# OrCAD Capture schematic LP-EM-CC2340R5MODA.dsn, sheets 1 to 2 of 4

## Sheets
1 1_RF: size A3; title: LP-EM-CC2340R5MODA
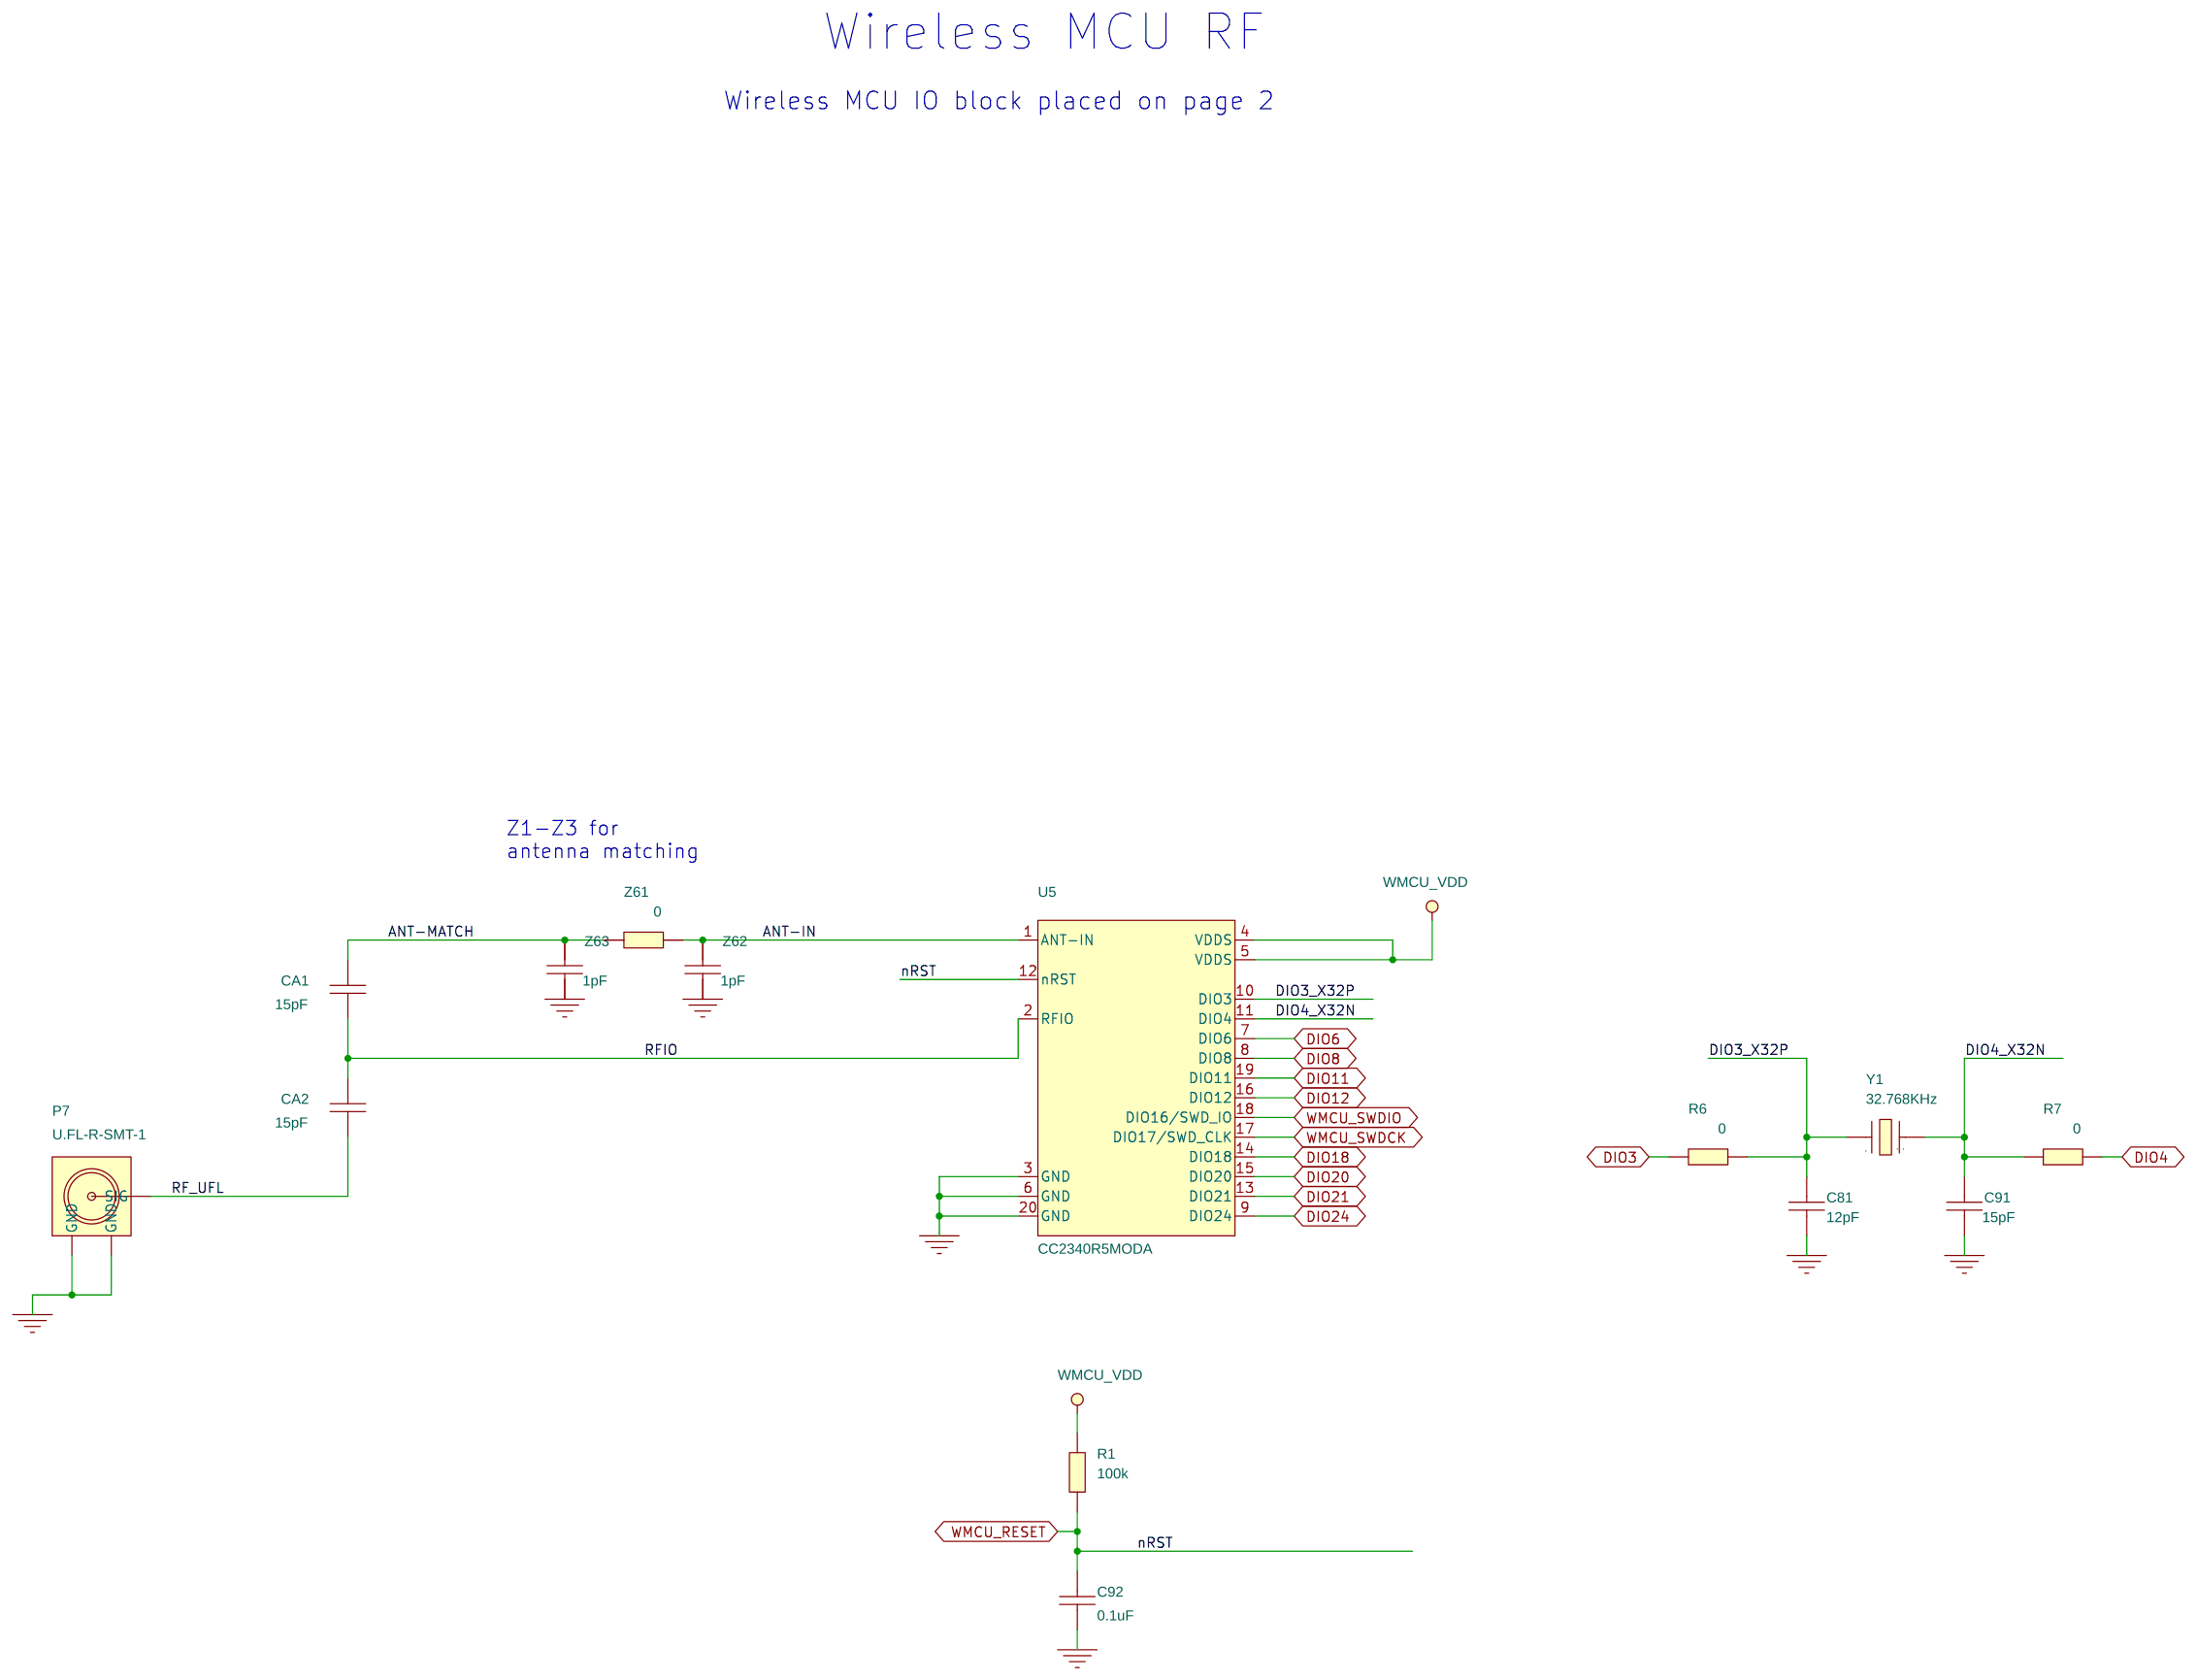
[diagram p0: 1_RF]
2 2_Peripherals: size A3
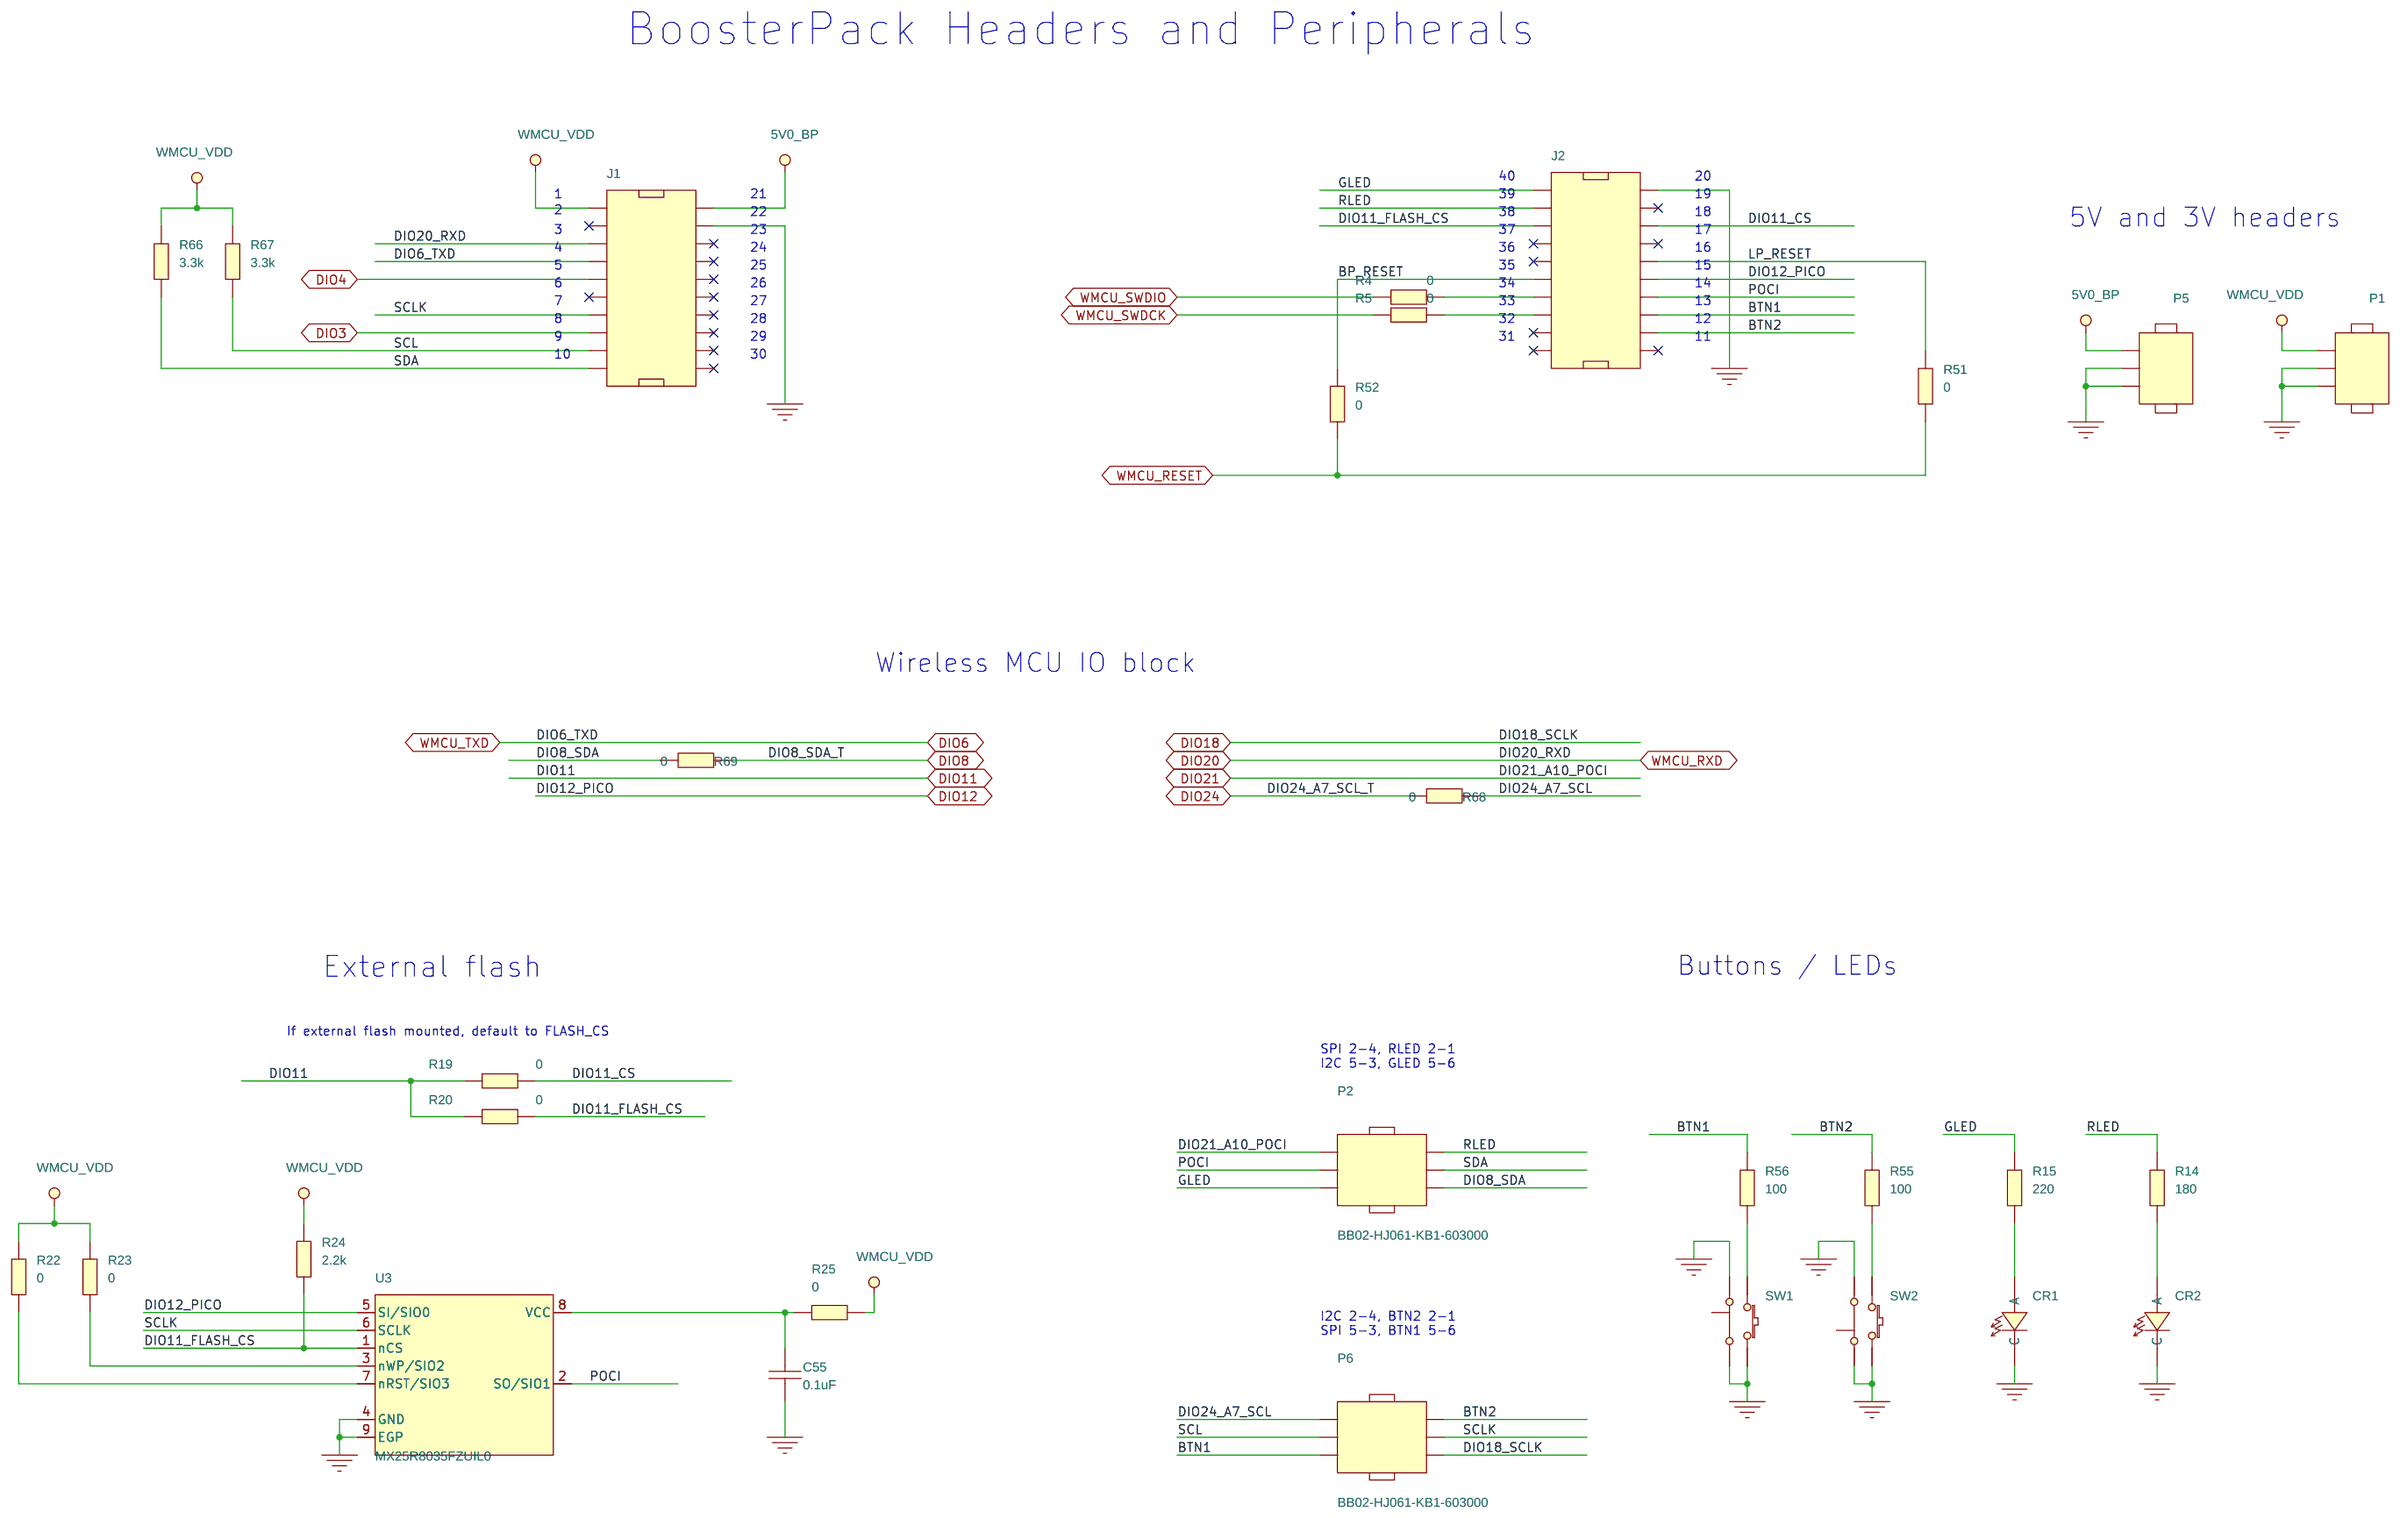
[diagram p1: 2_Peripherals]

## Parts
sheet 1_RF
C81  12pF  [CAPC0603X35B2N]
C91  15pF  [CAPC0603X35B2N]
C92  0.1uF  [CAPC0603X35B2N]
CA1  15pF  [CAPC0603X35B2N]
CA2  15pF  [CAPC0603X35B2N]
P7  U.FL-R-SMT-1  [HIROSE_UFLRSMT_A2N]
R1  100k  [RESC0603X35B2N]
R6  0  [RESC0603X35B2N]
R7  0  [RESC0603X35B2N]
U5  CC2340R5MODA  [MODULE_CC2340R5MODA_A2N]
Y1  32.768KHz  [XTAL_TZ3359DAAO73_A2N]
Z61  0  [RESC0603X35B2N]
Z62  1pF  [CAPC0603X35B2N]
Z63  1pF  [CAPC0603X35B2N]
sheet 2_Peripherals
C55  0.1uF  [CAPC0603X35B2N]
CR1  LPL296-J2L2-25  [LEDC1707X65N]
CR2  LS L296-P2Q2-1  [LEDC1708X67N]
J1  SSQ-110-23-L-D  [SAMTEC_SSQ11023LD_A2B]
J2  SSQ-110-23-L-D  [SAMTEC_SSQ11023LD_A2B]
P1  BB02-HC031-KB1-603000  [GRADCONN_BB02HC031KB1603000_A2B]
P2  BB02-HJ061-KB1-603000  [GRADCONN_BB02HJ061KB1603000_A2B]
P5  BB02-HC031-KB1-603000  [GRADCONN_BB02HC031KB1603000_A2B]
P6  BB02-HJ061-KB1-603000  [GRADCONN_BB02HJ061KB1603000_A2B]
R4  0  [RESC1608X55A2N]
R5  0  [RESC1608X55A2N]
R14  180  [RESC1005X40B2N]
R15  220  [RESC1005X40B2N]
R19  0  [RESC1608X55A2N]
R20  0  [RESC1608X55A2N]
R22  0  [RESC1608X55A2N]
R23  0  [RESC1608X55A2N]
R24  2.2k  [RESC1005X40B2N]
R25  0  [RESC1608X55A2N]
R51  0  [RESC1608X55A2N]
R52  0  [RESC1608X55A2N]
R55  100  [RESC1005X40B2N]
R56  100  [RESC1005X40B2N]
R66  3.3k  [RESC1005X40B2N]
R67  3.3k  [RESC1005X40B2N]
R68  0  [RESC1005X40A2N]
R69  0  [RESC1005X40A2N]
SW1  1188E-1K2  [SW_1188E1K2V_A2N]
SW2  1188E-1K2  [SW_1188E1K2V_A2N]
U3  MX25R8035FZUIL0  [SON50P300X200X60-9B2N]

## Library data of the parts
C81 = CAPACITOR: CAPACITOR, CERAMIC C0G/NP0, 12pF, 50V, -2%/+2%, -55DEGC/+125DEGC, 0201, SMD; ALT_SYMBOLS: CAPC0603X35B2L,CAPC0603X35B2M; Additional Datasheet URL: https://www.murata.com/en-us/products/productdetail?partno=GRM0335C1H120GA01%23; AutoDoc File: https://notefied-dynamic-precision.com/DB/Apps/Desktop/Item/Object.aspx?id=113345; BU Name: TEXAS INSTRUMENTS NORWAY; Budget Currency: EUR; Budget Price: 0.007; Budgetary Price: .00506 USD; Country of Origin: China, Japan, Philippines; Datasheet URL: https://search.murata.co.jp/Ceramy/image/img/A01X/G101/ENG/GRM0335C1H120GA01-01A.pdf; Datasheet URL 1: http://psearch.murata.com/capacitor/product/GRM1555C1H120JA01%23.pdf; Datasheet URL 2: http://search.murata.co.jp/Ceramy/image/img/w_hinm/L0005E.pdf; Definied Quality: INDUSTRIAL; Dielectric Type: C0G/NP0; Esd Level: N/A; Lead Time: 23; LifeCycle Status: ACTIVE; MPN: CAPACITOR_0402_12pF_C0G/NP0_M_+/-5%_50V; MPN Status: ACTIVE; MSL: N/A; MTBF: N/A; MTBF Standard: N/A; Manufacturer: MANUFACTURER SELECTION; Mass: 0.00033g; Max Oper Temp: +125DEGC; Max Tol: +5%; Maximum Operating Temperature: +125DEGC; Maximum Tolerance: +2%; Min Oper Temp: -55DEGC; Min Tol: -5%; Minimum Operating Temperature: -55DEGC; Minimum Tolerance: -2%; Mounting Type: SMD; NOTE Status: PREFERRED; NOTEfied URL: https://dev-webinterface.dpserver.no/item/31254676; Old Footprint: CAPC1005X60N; PCB Package: 0201; Packing Size: 15000; Packing Type: Tape & Reel; Part Number: 02-10307; Part Type: Capacitor|CERAMIC|0201|STANDARD; REACH/SVHC Compliance: Compliant; REACH/SVHC Details: SVHC List Version Jan 19, 2021; REACH/SVHC Source: REACH Declaration; REACH/SVHC Status: Unaffected; REACH/SVHC_COMPLIANCE: COMPLIANT; REACH/SVHC_DETAILS: SVHC LIST VERSION Dec 17, 2015; REACH/SVHC_SOURCE: REACH DECLARATION; REACH/SVHC_STATUS: UNAFFECTED; ROHS: Compliant; Rated Voltage: 50V; Revision: R003; RoHS Status: ROHS_COMPLIANT; Rtd Voltage: 50V; Status: Released; Texas Part Status: Under Review; Type: Capacitor; Vendor: MURATA; Vendor Part Number: GRM0335C1H120GA01D; Vendor Part Status: Active; WEIGHT: 0.0016g
C91 = CAPACITOR: CAPACITOR, CERAMIC C0G/NP0, 15pF, 50V, -2%/+2%, -55DEGC/+125DEGC, 0201, SMD; ALT_SYMBOLS: CAPC0603X35B2L,CAPC0603X35B2M; Additional Datasheet URL: https://www.murata.com/en-us/products/productdetail?partno=GRM0335C1H150GA01%23; AutoDoc File: https://notefied-dynamic-precision.com/DB/Apps/Desktop/Item/Object.aspx?id=114571; BU Name: TEXAS INSTRUMENTS NORWAY; Budget Currency: EUR; Budget Price: 0.006; Budgetary Price: .0032 USD; Client Status: UNDER_REVIEW; Country of Origin: China, Japan, Philippines; Datasheet URL: https://search.murata.co.jp/Ceramy/image/img/A01X/G101/ENG/GRM0335C1H150GA01-01A.pdf; Datasheet URL 1: http://psearch.murata.com/capacitor/product/GRM1555C1H150JA01%23.pdf; Datasheet URL 2: http://psearch.en.murata.com/capacitor/product/GRM1555C1H150JA01%23.html; Definied Quality: INDUSTRIAL; Dielectric Type: C0G/NP0; Esd Level: N/A; Lead Time: 11; LifeCycle Status: ACTIVE; MPN: CAPACITOR_0402_12pF_C0G/NP0_M_+/-5%_50V; MPN Status: ACTIVE; MSL: N/A; MTBF: N/A; MTBF Standard: N/A; Manufacturer: MANUFACTURER SELECTION; Mass: 0.00033g; Max Oper Temp: +125DEGC; Max Tol: +5%; Maximum Operating Temperature: +125DEGC; Maximum Tolerance: +2%; Min Oper Temp: -55DEGC; Min Tol: -5%; Minimum Operating Temperature: -55DEGC; Minimum Tolerance: -2%; Mounting Type: SMD; NOTE Status: PREFERRED; NOTEfied URL: https://dev-webinterface.dpserver.no/item/20744949; Old Footprint: CAPC1005X60N; PCB Package: 0201; Packing Size: 15000; Packing Type: Tape & Reel; Part Number: 02-09323; Part Type: Capacitor|CERAMIC|0201|STANDARD; REACH/SVHC Compliance: Compliant; REACH/SVHC Details: SVHC List Version Jan 15, 2019; REACH/SVHC Source: REACH Declaration; REACH/SVHC Status: Unaffected; REACH/SVHC_COMPLIANCE: COMPLIANT; REACH/SVHC_DETAILS: SVHC List Version Jan 12, 2017; REACH/SVHC_SOURCE: REACH DECLARATION; REACH/SVHC_STATUS: UNAFFECTED; ROHS: Compliant; Rated Voltage: 50V; Revision: R010; RoHS Status: ROHS_COMPLIANT; Rtd Voltage: 50V; Status: Released; Texas Part Status: Under Review; Type: Capacitor; Vendor: MURATA; Vendor Part Number: GRM0335C1H150GA01D; Vendor Part Status: Active; WEIGHT: 0.0016g
C92 = CAPACITOR: CAPACITOR, CERAMIC X7S, 0.1uF, 10V, -10%/+10%, -55DEGC/+125DEGC, 0201, SMD; ALT_SYMBOLS: CAPC0603X35B2L,CAPC0603X35B2M; Additional Datasheet URL: https://www.murata.com/en-us/products/productdetail?partno=GRM033C71A104KE14%23; AutoDoc File: https://notefied-dynamic-precision.com/DB/Apps/Desktop/Item/Object.aspx?id=115293; BU Name: TEXAS INSTRUMENTS NORWAY; Budgetary Price: .01328 USD; Client Status: UNDER_REVIEW; Country of Origin: China, Japan, Philippines, Singapore; Datasheet URL: https://search.murata.co.jp/Ceramy/image/img/A01X/G101/ENG/GRM033C71A104KE14-01A.pdf; Datasheet URL 1: http://psearch.en.murata.com/capacitor/product/GRM155R71E104KE14%23.pdf; Datasheet URL 2: http://search.murata.co.jp/Ceramy/image/img/w_hinm/L0005E.pdf; Dielectric Type: X7S; Lead Time: 23; LifeCycle Status: ACTIVE; MPN: GRM155R70J104KA01D; MPN Status: ACTIVE; Manufacturer: MURATA; Mass: 0.00033g; Max Oper Temp: +125DEGC; Max Tol: +10%; Maximum Operating Temperature: +125DEGC; Maximum Tolerance: +10%; Min Oper Temp: -55DEGC; Min Tol: -10%; Minimum Operating Temperature: -55DEGC; Minimum Tolerance: -10%; Mounting Type: SMD; NOTE Status: PREFERRED; NOTEfied URL: https://dev-webinterface.dpserver.no/item/31254761; Old Footprint: CAPC1005X60N,0402; PCB Package: 0201; Packing Size: 15000; Packing Type: Tape & Reel; Part Number: 02-10308; Part Type: Capacitor|CERAMIC|0201|STANDARD; REACH/SVHC Compliance: Compliant; REACH/SVHC Details: SVHC List Version Jan 19, 2021; REACH/SVHC Source: REACH Declaration; REACH/SVHC Status: Unaffected; REACH/SVHC_COMPLIANCE: COMPLIANT; REACH/SVHC_DETAILS: SVHC LIST VERSION Jun 20, 2016; REACH/SVHC_SOURCE: REACH DECLARATION; REACH/SVHC_STATUS: UNAFFECTED; ROHS: Compliant; Rated Voltage: 10V; Revision: R003; RoHS Status: ROHS_COMPLIANT; Rtd Voltage: 25V; Status: Released; Texas Part Status: Under Review; Type: Capacitor; Vendor: MURATA; Vendor Part Number: GRM033C71A104KE14D; Vendor Part Status: Active; WEIGHT: 0.0016g
CA1 CA2 = CAPACITOR: CAPACITOR, CERAMIC C0G/NP0, 15pF, 50V, -2%/+2%, -55DEGC/+125DEGC, 0201, SMD; ALT_SYMBOLS: CAPC0603X35B2L,CAPC0603X35B2M; Additional Datasheet URL: https://www.murata.com/en-us/products/productdetail?partno=GRM0335C1H150GA01%23; AutoDoc File: https://notefied-dynamic-precision.com/DB/Apps/Desktop/Item/Object.aspx?id=113345; BU Name: TEXAS INSTRUMENTS NORWAY; Budget Currency: EUR; Budget Price: 0.007; Budgetary Price: .0032 USD; Country of Origin: China, Japan, Philippines; Datasheet URL: https://search.murata.co.jp/Ceramy/image/img/A01X/G101/ENG/GRM0335C1H150GA01-01A.pdf; Datasheet URL 1: http://psearch.murata.com/capacitor/product/GRM1555C1H120JA01%23.pdf; Datasheet URL 2: http://search.murata.co.jp/Ceramy/image/img/w_hinm/L0005E.pdf; Definied Quality: INDUSTRIAL; Dielectric Type: C0G/NP0; Esd Level: N/A; Lead Time: 11; LifeCycle Status: ACTIVE; MPN: CAPACITOR_0402_12pF_C0G/NP0_M_+/-5%_50V; MPN Status: ACTIVE; MSL: N/A; MTBF: N/A; MTBF Standard: N/A; Manufacturer: MANUFACTURER SELECTION; Mass: 0.00033g; Max Oper Temp: +125DEGC; Max Tol: +5%; Maximum Operating Temperature: +125DEGC; Maximum Tolerance: +2%; Min Oper Temp: -55DEGC; Min Tol: -5%; Minimum Operating Temperature: -55DEGC; Minimum Tolerance: -2%; Mounting Type: SMD; NOTE Status: PREFERRED; NOTEfied URL: https://dev-webinterface.dpserver.no/item/20744949; Old Footprint: CAPC1005X60N; PCB Package: 0201; Packing Size: 15000; Packing Type: Tape & Reel; Part Number: 02-09323; Part Type: Capacitor|CERAMIC|0201|STANDARD; REACH/SVHC Compliance: Compliant; REACH/SVHC Details: SVHC List Version Jan 15, 2019; REACH/SVHC Source: REACH Declaration; REACH/SVHC Status: Unaffected; REACH/SVHC_COMPLIANCE: COMPLIANT; REACH/SVHC_DETAILS: SVHC LIST VERSION Dec 17, 2015; REACH/SVHC_SOURCE: REACH DECLARATION; REACH/SVHC_STATUS: UNAFFECTED; ROHS: Compliant; Rated Voltage: 50V; Revision: R010; RoHS Status: ROHS_COMPLIANT; Rtd Voltage: 50V; Status: Released; Texas Part Status: Under Review; Type: Capacitor; Vendor: MURATA; Vendor Part Number: GRM0335C1H150GA01D; Vendor Part Status: Active; WEIGHT: 0.0016g
P7 = CONN_COAX_1_P_2_UFL: CONNECTOR, COAX, RF, MALE, STRAIGHT, 1 PIN(S), SMD; ALT_SYMBOLS: HIROSE_UFLRSMT_A2L,HIROSE_UFLRSMT_A2M; Additional Datasheet URL: https://www.hirose.com/en/product/p/CL0331-0472-2-01; Budgetary Price: .7575 USD; CLASS: IO; Country of Origin: Japan; Datasheet URL: https://www.hirose.com/en/product/document?clcode=CL0331-0472-2-01&productname=U.FL-R-SMT-1(01)&series=U.FL&documenttype=Catalog&lang=en&documentid=en_U.FL_CAT; Lead Time: 12; Mass: 0.0157g; Maximum Operating Temperature: +105DEGC; Minimum Operating Temperature: -40DEGC; Mounting Type: SMD; NOTEfied URL: https://dev-webinterface.dpserver.no/item/7312664; Number of Positions: 1; Packing Size: 100; Packing Type: Bag; Part Number: 06-01471; Part Type: Connector|COAX|RF; ROHS: Compliant; Rated Current: N/A; Rated Voltage: 200V; Status: Released; Type: Connector; Vendor: HIROSE; Vendor Part Number: U.FL-R-SMT-1(01); Vendor Part Status: Active
R1 = RESISTOR: RESISTOR, THICK FILM, 100k, -5%/+5%, 0.05W, 30V, -55DEGC/+155DEGC, 0201, SMD; ALT_SYMBOLS: RESC0603X35B2L,RESC0603X35B2M; Additional Datasheet URL: https://www.vishay.com/en/product/20052/; Budgetary Price: .005 EUR; Country of Origin: China, Israel, Taiwan; Datasheet URL: https://www.vishay.com/docs/20052/crcw0201e3.pdf; Lead Time: 20; Mass: 0.00017g; Maximum Operating Temperature: +155DEGC; Maximum Temperature Coefficient: +200PPM/DEGC; Maximum Tolerance: +5%; Minimum Operating Temperature: -55DEGC; Minimum Temperature Coefficient: -200PPM/DEGC; Minimum Temperature Coeficient: -200PPM/DEGC; Minimum Tolerance: -5%; Mounting Type: SMD; NOTEfied URL: https://dev-webinterface.dpserver.no/item/7195810; PCB Package: 0201; Packing Size: 10000; Packing Type: Tape & Reel; Part Number: 01-04220; Part Type: Resistor|0201|STANDARD; REACH/SVHC Compliance: Compliant; REACH/SVHC Details: SVHC List Version Dec 17, 2015; REACH/SVHC Source: Material Declaration; REACH/SVHC Status: Unaffected; ROHS: Exempt; Rated Current: N/A; Rated Power: 0.05W; Rated Voltage: 30V; Resistor Type: THICK FILM; Revision: R008; Status: Released; Texas Part Number: TEXAS_00013; Texas Part Status: Under Review; Type: Resistor; Vendor: VISHAY; Vendor Part Number: CRCW0201100KJNED; Vendor Part Status: Active
R6 R7 Z61 = RESISTOR: RESISTOR, THICK FILM, JUMPER, 0, 0R/+0.05R, 0.5A, -55DEGC/+125DEGC, 0201, SMD; ALT_SYMBOLS: RESC0603X35B2L,RESC0603X35B2M; Additional Datasheet URL: https://www.koaspeer.com/products/resistors/general-purpose/rk73z/; Budgetary Price: .012 EUR; Country of Origin: Missing Info; Datasheet URL: https://www.koaspeer.com/pdfs/RK73Z.pdf; Lead Time: 14; Mass: 0.00014g; Maximum Operating Temperature: +125DEGC; Maximum Temperature Coefficient: N/A; Maximum Tolerance: +0.05R; Minimum Operating Temperature: -55DEGC; Minimum Temperature Coefficient: N/A; Minimum Temperature Coeficient: N/A; Minimum Tolerance: 0R; Mounting Type: SMD; NOTEfied URL: https://dev-webinterface.dpserver.no/item/7239994; PCB Package: 0201; Packing Size: 10000; Packing Type: Tape & Reel; Part Number: 01-18293; Part Type: Resistor|0201|JUMPER; ROHS: Exempt; Rated Current: 0.5A; Rated Power: N/A; Rated Voltage: N/A; Resistor Type: THICK FILM; Revision: R013; Status: Released; Type: Resistor; Vendor: KOA SPEER; Vendor Part Number: RK73Z1HTTC; Vendor Part Status: NRND
U5 = IC_RF_CC2340R5MODA: IC, MODULE, CC2340R5MODA; Additional Datasheet URL: https://www.ti.com/; Country of Origin: Missing Info; Datasheet URL: N/A; Mass: N/A; Maximum Operating Temperature: N/A; Minimum Operating Temperature: N/A; Mounting Type: SMD; NOTEfied URL: https://dev-webinterface.dpserver.no/item/59600491; Notes: Custom item; Packing Size: N/A; Packing Type: Missing Info; Part Number: 18-39305; Part Type: IC|MODULE|WIRELESS; ROHS: Missing Info; Status: Released; Texas Part Status: Under Review; Type: IC; Vendor: TEXAS INSTRUMENTS; Vendor Part Status: Preliminary
Y1 = XTAL: CRYSTAL, RESONATOR, 32.768KHz, -380PPM/+380PPM, -40DEGC/+125DEGC, SMD; ALT_SYMBOLS: XTAL_TZ3359DAAO73_A2L,XTAL_TZ3359DAAO73_A2M; Additional Datasheet URL: https://www.taisaw.com/products/searchA?param=TZ3359DAAO73; Capacitance: 7pF; Country of Origin: Missing Info; Datasheet URL: https://www.taisaw.com/assets/PDF/TZ3359DAAO73%20_Rev.1.pdf; Maximum Operating Temperature: +125DEGC; Maximum Stability: +380PPM; Maximum Tolerance: +20PPM; Minimum Operating Temperature: -40DEGC; Minimum Stability: -380PPM; Minimum Tolerance: -20PPM; Mounting Type: SMD; NOTEfied URL: https://dev-webinterface.dpserver.no/item/34987642; Notes: Non-standard part/non-catalogue part. Created on the basis of documentation provided by the customer (Texas Instruments).; Packing Size: 5000; Packing Type: Tape & Reel; Part Number: 12-01593; Part Type: Crystal|RESONATOR; REACH/SVHC Compliance: Missing Info; REACH/SVHC Details: N/A; REACH/SVHC Source: N/A; REACH/SVHC Status: Missing Info; ROHS: Compliant; Revision: R001; Status: Released; Texas Part Status: Under Review; Type: Crystal; Vendor: TAI-SAW; Vendor Part Number: TZ3359DAAO73; Vendor Part Status: Active
Z62 Z63 = CAPACITOR: CAPACITOR, CERAMIC C0G/NP0, 1pF, -0.1pF/+0.1pF, 50V, -55DEGC/+125DEGC, 0201, SMD; ALT_SYMBOLS: CAPC0603X35B2L,CAPC0603X35B2M; Additional Datasheet URL: https://pim.murata.com/en-us/pim/details/?productCategoryId=ceramicCapacitorSMD&partNum=GRM0335C1H1R0BA01%23; Budgetary Price: .01 EUR; Country of Origin: China, Japan, Philippines, Singapore, Thailand; Datasheet URL: https://pim.murata.com/asset/pim4/ceramicCapacitorSMD/GRM0335C1H1R0BA01-01A-EN_PDF_CERAMICCAPACITORSMD?lastModifiedDatetime=20250813140542; Dielectric Type: C0G/NP0; Lead Time: 24; Mass: 0.00033g; Maximum Operating Temperature: +125DEGC; Maximum Tolerance: +0.1pF; Minimum Operating Temperature: -55DEGC; Minimum Tolerance: -0.1pF; Mounting Type: SMD; NOTEfied URL: https://webinterface.notefied-dynamic-precision.com/item/7272567; PCB Package: 0201; Packing Size: 50000; Packing Type: Tape & Reel; Part Number: 02-06124; Part Type: Capacitor|CERAMIC|0201|STANDARD; REACH/SVHC Compliance: Compliant; REACH/SVHC Details: SVHC List Version Jan 23, 2024 (240); REACH/SVHC Source: REACH Declaration; REACH/SVHC Status: Unaffected; ROHS: Compliant; Rated Voltage: 50V; Status: Released; Texas Part Status: Under Review; Type: Capacitor; Vendor: MURATA; Vendor Part Number: GRM0335C1H1R0BA01J; Vendor Part Status: Active
C55 = CAPACITOR: CAPACITOR, CERAMIC X7S, 0.1uF, 10V, -10%/+10%, -55DEGC/+125DEGC, 0201, SMD; ALT_SYMBOLS: CAPC0603X35B2L,CAPC0603X35B2M; Additional Datasheet URL: https://www.murata.com/en-us/products/productdetail?partno=GRM033C71A104KE14%23; AutoDoc File: https://notefied-dynamic-precision.com/DB/Apps/Desktop/Item/Object.aspx?id=115293; BU Name: TEXAS INSTRUMENTS NORWAY; Budgetary Price: .01328 USD; Client Status: UNDER_REVIEW; Country of Origin: China, Japan, Philippines, Singapore; Datasheet URL: https://search.murata.co.jp/Ceramy/image/img/A01X/G101/ENG/GRM033C71A104KE14-01A.pdf; Datasheet URL 1: http://psearch.en.murata.com/capacitor/product/GRM155R71E104KE14%23.pdf; Datasheet URL 2: http://search.murata.co.jp/Ceramy/image/img/w_hinm/L0005E.pdf; Definied Quality: INDUSTRIAL; Dielectric Type: X7S; Esd Level: N/A; Lead Time: 23; LifeCycle Status: ACTIVE; MPN: CAPACITOR_0402_100nF_X7R_M_+/-10%_10V; MPN Status: ACTIVE; MSL: N/A; MTBF: N/A; MTBF Standard: N/A; Manufacturer: MANUFACTURER SELECTION; Mass: 0.00033g; Max Oper Temp: +125DEGC; Max Tol: +10%; Maximum Operating Temperature: +125DEGC; Maximum Tolerance: +10%; Min Oper Temp: -55DEGC; Min Tol: -10%; Minimum Operating Temperature: -55DEGC; Minimum Tolerance: -10%; Mounting Type: SMD; NOTE Status: PREFERRED; NOTEfied URL: https://dev-webinterface.dpserver.no/item/31254761; Old Footprint: CAPC1005X60N; PCB Package: 0201; Packing Size: 15000; Packing Type: Tape & Reel; Part Number: 02-10308; Part Type: Capacitor|CERAMIC|0201|STANDARD; REACH/SVHC Compliance: Compliant; REACH/SVHC Details: SVHC List Version Jan 19, 2021; REACH/SVHC Source: REACH Declaration; REACH/SVHC Status: Unaffected; REACH/SVHC_COMPLIANCE: COMPLIANT; REACH/SVHC_DETAILS: SVHC LIST VERSION Jun 20, 2016; REACH/SVHC_SOURCE: REACH DECLARATION; REACH/SVHC_STATUS: UNAFFECTED; ROHS: Compliant; Rated Voltage: 10V; Revision: R003; RoHS Status: ROHS_COMPLIANT; Rtd Voltage: 25V; Status: Released; Texas Part Status: Under Review; Type: Capacitor; Vendor: MURATA; Vendor Part Number: GRM033C71A104KE14D; Vendor Part Status: Active; WEIGHT: 0.0016g
CR1 = LED: OPTO, LED, InGaAlP, GREEN, 560nm, 1.8V TO 2.4V, 0.02A, 0603, SMD; ALT_SYMBOLS: LEDC1707X65L,LEDC1707X65M; Additional Datasheet URL: https://ams-osram.com/products/leds/color-leds/osram-smartled-0603-lp-l296; AutoDoc File: http://notefied-dynamic-precision.com/DB/Apps/Desktop/Item/Object.aspx?id=81622; Budget Currency: USD; Budget Price: 0.1263; CLASS: IC; Country of Origin: Missing Info; Datasheet URL: https://look.ams-osram.com/m/37da308c02be71bd/original/LP-L296.pdf; Datasheet URL 1: N/A; Datasheet URL 2: http://catalog.osram-os.com/jsp/download.jsp?rootPath=/media/&name=LP_L296.pdf&docPath=Graphics/00077128_0.pdf&url=/media//_en/Graphics/00077128_0.pdf; Definied Quality: INDUSTRIAL; Esd Level: HBM 2kV; FPLIST: LEDC1707X65N,LEDC1707X65L,LEDC1707X65M; MPN: LP L296-J2L2-25; MPN Status: NRND; MSL: 2; MTBF: N/A; MTBF Standard: N/A; Manufacturer: OSRAM; Mass: 0.0016g; Max Oper Temp: +100DEGC; Maximum Operating Temperature: +100DEGC; Min Oper Temp: -40DEGC; Minimum Operating Temperature: -40DEGC; Mounting Type: SMD; NOTE Status: NOT_PREFERRED; NOTEfied URL: https://dev-webinterface.dpserver.no/item/7373913; PCB Package: 0603; Packing Size: 5000; Packing Type: Tape & Reel; Part Number: 15-01023; Part Type: Opto|LED|0603; REACH/SVHC Compliance: Compliant; REACH/SVHC Details: SVHC List Version Jan 12, 2017; REACH/SVHC Source: REACH Declaration; REACH/SVHC Status: Unaffected; ROHS: Compliant; Rated Current: 0.02A; Rated Voltage: 1.8V TO 2.4V; Revision: R033; RoHS Status: ROHS_COMPLIANT; Rtd Current: 0.02A; Rtd Power: 0.08W; Rtd Voltage: 2V; Status: Released; Type: Opto; Vendor: OSRAM; Vendor Part Number: LP L296-J2L2-25; Vendor Part Status: Active; WEIGHT: 0.002g
CR2 = LED: OPTO, LED, RED, 630nm, 1.8V TO 2.3V, 0.02A, 0603, SMD; ALT_SYMBOLS: LEDC1708X67L,LEDC1708X67M; Additional Datasheet URL: https://ams-osram.com/products/leds/color-leds/osram-smartled-0603-ls-l296; AutoDoc File: http://notefied-dynamic-precision.com/DB/Apps/Desktop/Item/Object.aspx?id=88355; Budget Currency: USD; Budget Price: 0.089; CLASS: IC; Country of Origin: Missing Info; Datasheet URL: https://look.ams-osram.com/m/1ce9402ea49508df/original/LS-L296.pdf; Datasheet URL 1: http://www.osram-os.com/osram_os/en/products/product-catalog/led-light-emitting-diodes/smartled-0603/ls-l296/index.jsp?search_result=%2fosram_os%2fen%2fsearch%2fadvanced_search.jsp%3faction%3ddosearch%26inp_searchterm_1%3dLS%2bL296-P2Q2-1%26website_name%3; Datasheet URL 2: http://www.osram-os.com/Graphics/XPic5/00077119_0.pdf/LS%20L296%20-%20SMARTLED%200603.pdf; Definied Quality: INDUSTRIAL; Esd Level: HBM 2kV; FPLIST: LEDC1708X67N,LEDC1708X67L,LEDC1708X67M; MPN Status: NRND; MSL: 2; MTBF: N/A; MTBF Standard: N/A; Manufacturer: OSRAM; Mass: 0.0016g; Max Oper Temp: +100DEGC; Maximum Operating Temperature: +100DEGC; Min Oper Temp: -40DEGC; Minimum Operating Temperature: -40DEGC; Mounting Type: SMD; NOTE Status: PREFERRED; NOTEfied URL: https://dev-webinterface.dpserver.no/item/7374561; PCB Package: 0603; PPCB Recomendation: Inactive for new design [Alert:0001]; Packing Size: 5000; Packing Type: Tape & Reel; Part Number: 15-01169; Part Type: Opto|LED|0603; REACH/SVHC Compliance: Compliant; REACH/SVHC Details: SVHC List Version Jan 12, 2017; REACH/SVHC Source: REACH Declaration; REACH/SVHC Status: Unaffected; ROHS: Compliant; Rated Current: 0.02A; Rated Voltage: 1.8V TO 2.3V; Revision: R034; RoHS Status: ROHS_COMPLIANT; Rtd Current: 0.06A; Rtd Voltage: 1.8V TO 2.3V; Status: Released; Type: Opto; Vendor: OSRAM; Vendor Part Status: Active; WEIGHT: 0.002g
J1 J2 = CONN_HEADER_2X10_J_S_V1: CONNECTOR, HEADER, FEMALE, STRAIGHT, 2 ROW(S), 20 PIN(S), 2.54mm, PTH; ALT_SYMBOLS: SAMTEC_SSQ11023LD_A2A,SAMTEC_SSQ11023LD_A2C; Additional Datasheet URL: https://www.samtec.com/products/ssq-110-23-l-d; AutoDoc File: http://notefied-dynamic-precision.com/DB/Apps/Desktop/Item/Object.aspx?id=104387; Budget Currency: USD; Budget Price: 2.14; Budgetary Price: 2.62146 USD; Country of Origin: China, Costa Rica, Malaysia, Singapore, Taiwan, United States, Vietnam; Datasheet URL: https://suddendocs.samtec.com/catalog_english/ssq_th.pdf; Datasheet URL 1: http://suddendocs.samtec.com/prints/ssq-1xx-xx-xxx-x-xx-xxx-xx-x-mkt.pdf; Datasheet URL 2: http://suddendocs.samtec.com/catalog_english/ssq_th.pdf; Definied Quality: INDUSTRIAL; Esd Level: N/A; FPLIST: SAMTEC_SSQ11023LD_A2B,SAMTEC_SSQ11023LD_A2C,SAMTEC_SSQ11023LD_A2A; Lead Time: 12; LifeCycle Status: ACTIVE; MPN Status: ACTIVE; MSL: N/A; Manufacturer: SAMTEC; Mass: 2.45594g; Max Oper Temp: +125DEGC; Maximum Operating Temperature: +125DEGC; Min Oper Temp: -55DEGC; Minimum Operating Temperature: -55DEGC; Mounting Type: PTH; NOTE Status: PREFERRED; NOTEfied URL: https://dev-webinterface.dpserver.no/item/7324084; No Of Pos: 20; No Of Rows: 2; Number of Positions: 20; Number of Rows: 2; Packing Size: 21; Packing Type: Bulk; Part Number: 06-04997; Part Type: Connector|HEADER|STANDARD; Pitch: 2.54mm; REACH/SVHC Compliance: Compliant; REACH/SVHC Details: SVHC List Version Jan 12, 2017; REACH/SVHC Source: REACH Declaration; REACH/SVHC Status: Unaffected; ROHS: Compliant; Rated Current: 6.3A; Rated Voltage: 465VAC / 655VDC; Revision: R022; RoHS Status: ROHS_COMPLIANT; Rtd Current: 6.3A; Status: Released; Texas Part Status: Under Review; Type: Connector; Vendor: SAMTEC; Vendor Part Status: Active; WEIGHT: 2.45594g
P1 P5 = CONN_HEADER_3_P_S: CONNECTOR, HEADER, MALE, STRAIGHT, 1 ROW(S), 3 PIN(S), PITCH 2.54mm, PTH; ALT_SYMBOLS: GRADCONN_BB02HC031KB1603000_A2A,GRADCONN_BB02HC031KB1603000_A2C; Additional Datasheet URL: https://www.gradconn.com/Products/BoardToBoard/All/BB02-HC; AutoDoc File: http://notefied-dynamic-precision.com/DB/Apps/Desktop/Item/Object.aspx?id=104636; Country of Origin: Missing Info; Datasheet URL: https://www.gradconn.com/files/Drawings/BB02-HC.pdf; Datasheet URL 1: http://www.gradconn.com/Files/Drawings/BB02-HC.pdf; Datasheet URL 2: http://www.gradconn.com/Files/Specs/BTB-2.54mm-Header-specification.pdf; MPN Status: ACTIVE; Manufacturer: GRADCONN; Mass: N/A; Max Oper Temp: +105DEGC; Maximum Operating Temperature: +105DEGC; Min Oper Temp: -40DEGC; Minimum Operating Temperature: -40DEGC; Mounting Type: PTH; NOTE Status: PREFERRED; NOTEfied URL: https://dev-webinterface.dpserver.no/item/7324030; No Of Pos: 3; No Of Rows: 1; Number of Positions: 3; Number of Rows: 1; Packing Size: N/A; Packing Type: Missing Info; Part Number: 06-05038; Part Type: Connector|HEADER|STANDARD; Pitch: 2.54mm; REACH/SVHC Compliance: Compliant; REACH/SVHC Details: SVHC List Version Jun 20, 2016; REACH/SVHC Source: RoHS & REACH Declaration; REACH/SVHC Status: Unaffected; ROHS: Compliant; Rated Current: 3A; Rated Voltage: 250V; Revision: R023; RoHS Status: ROHS_COMPLIANT; Rtd Current: 3A; Rtd Voltage: 250V; Status: Released; Texas Part Status: Under Review; Type: Connector; Vendor: GRADCONN; Vendor Part Status: Active
P2 P6 = CONN_HEADER_2X3_P_V2: CONNECTOR, HEADER, MALE, STRAIGHT, 2 ROW(S), 6 PIN(S), PITCH 2.54mm, PTH; ALT_SYMBOLS: GRADCONN_BB02HJ061KB1603000_A2A,GRADCONN_BB02HJ061KB1603000_A2C; Additional Datasheet URL: https://www.gradconn.com/Products/BoardToBoard/All/BB02-HJ; Country of Origin: Missing Info; Datasheet URL: https://www.gradconn.com/files/Drawings/BB02-HJ.pdf; Maximum Operating Temperature: +105DEGC; Minimum Operating Temperature: -40DEGC; Mounting Type: PTH; NOTEfied URL: https://dev-webinterface.dpserver.no/item/30968420; Number of Positions: 6; Number of Rows: 2; Packing Size: N/A; Packing Type: Loose; Part Number: 06-10909; Part Type: Connector|HEADER|STANDARD; Pitch: 2.54mm; REACH/SVHC Compliance: Compliant; REACH/SVHC Details: SVHC List Version Jun 25, 2020; REACH/SVHC Source: RoHS & REACH Declaration; REACH/SVHC Status: Unaffected; ROHS: Compliant; Rated Current: 3A; Revision: R003; Status: Released; Texas Part Status: Under Review; Type: Connector; Vendor: GRADCONN; Vendor Part Status: Active
R4 R5 R19 R20 R22 R23 R25 R51 R52 = RESISTOR: RESISTOR, THICK FILM, JUMPER, 0, 0R/+0.02R, 0.1W, 2A, -55DEGC/+155DEGC, 0603, SMD; ALT_SYMBOLS: RESC1608X55A2L,RESC1608X55A2M; Additional Datasheet URL: N/A; AutoDoc File: https://notefied-dynamic-precision.com/DB/Apps/Desktop/Item/Object.aspx?id=94847; BU Name: DYNAMIC PRECISION GDANSK; Budget Currency: USD; Budget Price: 0.0016; Budgetary Price: .005 EUR; Client Status: UNDER_REVIEW; Country of Origin: Israel; Datasheet URL: http://www.vishay.com/docs/20035/dcrcwe3.pdf; Datasheet URL 1: http://www.vishay.com/docs/20035/dcrcwe3.pdf; Datasheet URL 2: N/A; Esd Level: N/A; Lead Time: 29; LifeCycle Status: ACTIVE; MPN: DNM; MPN Status: ACTIVE; MSL: N/A; MTBF: N/A; MTBF Standard: N/A; Manufacturer: DO NOT MOUNT; Mass: 0.002g; Max Oper Temp: +155DEGC; Max TC: N/A; Max Tol: +0.02R; Maximum Operating Temperature: +155DEGC; Maximum Temperature Coefficient: N/A; Maximum Tolerance: +0.02R; Min Oper Temp: -55DEGC; Min TC: N/A; Min Tol: 0R; Minimum Operating Temperature: -55DEGC; Minimum Temperature Coefficient: N/A; Minimum Temperature Coeficient: N/A; Minimum Tolerance: 0R; Mounting Type: SMD; NOTE Status: PREFERRED; NOTEfied URL: https://dev-webinterface.dpserver.no/item/7245735; Old Footprint: RESC1608X55N,0603; PCB Package: 0603; Packing Size: 20000; Packing Type: Tape & Reel; Part Number: 01-20043; Part Type: Resistor|0603|JUMPER; REACH/SVHC Compliance: Compliant; REACH/SVHC Details: SVHC List Version Jun 15, 2015; REACH/SVHC Source: Material Declaration; REACH/SVHC Status: Unaffected; REACH/SVHC_COMPLIANCE: COMPLIANT; REACH/SVHC_DETAILS: SVHC LIST VERSION Jun 15, 2015; REACH/SVHC_SOURCE: MATERIAL DECLARATION; REACH/SVHC_STATUS: UNAFFECTED; ROHS: Exempt; Rated Current: 2A; Rated Power: 0.1W; Rated Voltage: N/A; Resistor Type: THICK FILM; Revision: R010; RoHS Status: ROHS_COMPLIANT_WITH_EXEMPTION; Rtd Current: N/A; Rtd Power: 0.1W; Rtd Voltage: 75V; Status: Released; Type: Resistor; Vendor: VISHAY; Vendor Part Number: CRCW06030000Z0EC; Vendor Part Status: Active; WEIGHT: 0.002g
R14 = RESISTOR: RESISTOR, THICK FILM, 180, -5%/+5%, 0.063W, 50V, -55DEGC/+155DEGC, 0402, SMD; Additional Datasheet URL: https://www.vishay.com/en/product/20035/; AutoDoc File: https://notefied-dynamic-precision.com/DB/Apps/Desktop/Item/Object.aspx?id=113318; BU Name: TEXAS INSTRUMENTS NORWAY; Budget Currency: EUR; Budget Price: 0.014; Budgetary Price: .014 EUR; Client Status: UNDER_REVIEW; Country of Origin: China, Israel; Datasheet URL: https://www.vishay.com/docs/20035/dcrcwe3.pdf; Datasheet URL 1: http://www.vishay.com/docs/20035/dcrcwe3.pdf; Datasheet URL 2: N/A; Definied Quality: INDUSTRIAL; Esd Level: N/A; Lead Time: 18; LifeCycle Status: ACTIVE; MPN: RESISTOR_0402_180_+/-5%_50V_0.063W_M_+/-200ppm; MPN Status: ACTIVE; MSL: N/A; MTBF: N/A; MTBF Standard: N/A; Manufacturer: MANUFACTURER SELECTION; Mass: 0.00065g; Max Oper Temp: +155DEGC; Max TC: +200PPM/DEGC; Max Tol: +5%; Maximum Operating Temperature: +155DEGC; Maximum Temperature Coefficient: +200PPM/DEGC; Maximum Tolerance: +5%; Min Oper Temp: -55DEGC; Min TC: -200PPM/DEGC; Min Tol: -5%; Minimum Operating Temperature: -55DEGC; Minimum Temperature Coefficient: -200PPM/DEGC; Minimum Temperature Coeficient: -200PPM/DEGC; Minimum Tolerance: -5%; Mounting Type: SMD; NOTE Status: PREFERRED; NOTEfied URL: https://dev-webinterface.dpserver.no/item/7253041; Notes: Standard item: Duplicate Reason: custom footprint for TEXAS INSTRUMENTS NORWAY.; Old Footprint: RESC1005X40N; PCB Package: 0402; Packing Size: 10000; Packing Type: Tape & Reel; Part Number: 01-22345; Part Type: Resistor|0402|STANDARD; REACH/SVHC Compliance: Compliant; REACH/SVHC Details: SVHC List Version Jun 20, 2016; REACH/SVHC Source: Material Declaration; REACH/SVHC Status: Unaffected; REACH/SVHC_COMPLIANCE: COMPLIANT; REACH/SVHC_DETAILS: SVHC LIST VERSION Jun 20, 2016; REACH/SVHC_SOURCE: MATERIAL DECLARATION; REACH/SVHC_STATUS: UNAFFECTED; ROHS: Exempt; Rated Current: N/A; Rated Power: 0.063W; Rated Voltage: 50V; Resistor Type: THICK FILM; Revision: R024; RoHS Status: ROHS_COMPLIANT_WITH_EXEMPTION; Rtd Current: N/A; Rtd Power: 0.063W; Rtd Voltage: 50V; Status: Released; Texas Part Status: Under Review; Type: Resistor; Vendor: VISHAY; Vendor Part Number: CRCW0402180RJNED; Vendor Part Status: Active; WEIGHT: 0.00065g
R15 = RESISTOR: RESISTOR, THICK FILM, 220, -5%/+5%, 0.063W, 50V, -55DEGC/+155DEGC, 0402, SMD; Additional Datasheet URL: https://www.vishay.com/en/product/20035/; AutoDoc File: https://notefied-dynamic-precision.com/DB/Apps/Desktop/Item/Object.aspx?id=113319; BU Name: TEXAS INSTRUMENTS NORWAY; Budget Currency: EUR; Budget Price: 0.014; Budgetary Price: .014 EUR; Client Status: UNDER_REVIEW; Country of Origin: China, Israel; Datasheet URL: https://www.vishay.com/docs/20035/dcrcwe3.pdf; Datasheet URL 1: http://www.vishay.com/docs/20035/dcrcwe3.pdf; Datasheet URL 2: N/A; Definied Quality: INDUSTRIAL; Esd Level: N/A; Lead Time: 18; LifeCycle Status: ACTIVE; MPN: RESISTOR_0402_220_+/-5%_50V_0.063W_M_+/-200ppm; MPN Status: ACTIVE; MSL: N/A; MTBF: N/A; MTBF Standard: N/A; Manufacturer: MANUFACTURER SELECTION; Mass: 0.00065g; Max Oper Temp: +155DEGC; Max TC: +200PPM/DEGC; Max Tol: +5%; Maximum Operating Temperature: +155DEGC; Maximum Temperature Coefficient: +200PPM/DEGC; Maximum Tolerance: +5%; Min Oper Temp: -55DEGC; Min TC: -200PPM/DEGC; Min Tol: -5%; Minimum Operating Temperature: -55DEGC; Minimum Temperature Coefficient: -200PPM/DEGC; Minimum Temperature Coeficient: -200PPM/DEGC; Minimum Tolerance: -5%; Mounting Type: SMD; NOTE Status: PREFERRED; NOTEfied URL: https://dev-webinterface.dpserver.no/item/7253039; Notes: Standard item: Duplicate Reason: custom footprint for TEXAS INSTRUMENTS NORWAY.; Old Footprint: RESC1005X40N; PCB Package: 0402; Packing Size: 10000; Packing Type: Tape & Reel; Part Number: 01-22346; Part Type: Resistor|0402|STANDARD; REACH/SVHC Compliance: Compliant; REACH/SVHC Details: SVHC List Version Jun 20, 2016; REACH/SVHC Source: Material Declaration; REACH/SVHC Status: Unaffected; REACH/SVHC_COMPLIANCE: COMPLIANT; REACH/SVHC_DETAILS: SVHC LIST VERSION Jun 20, 2016; REACH/SVHC_SOURCE: MATERIAL DECLARATION; REACH/SVHC_STATUS: UNAFFECTED; ROHS: Exempt; Rated Current: N/A; Rated Power: 0.063W; Rated Voltage: 50V; Resistor Type: THICK FILM; Revision: R024; RoHS Status: ROHS_COMPLIANT_WITH_EXEMPTION; Rtd Current: N/A; Rtd Power: 0.063W; Rtd Voltage: 50V; Status: Released; Texas Part Status: Under Review; Type: Resistor; Vendor: VISHAY; Vendor Part Number: CRCW0402220RJNED; Vendor Part Status: Active; WEIGHT: 0.00065g
R24 = RESISTOR: RESISTOR, THICK FILM, 2.2k, -5%/+5%, 0.063W, 50V, -55DEGC/+155DEGC, 0402, SMD; Additional Datasheet URL: https://www.vishay.com/en/product/20035/; AutoDoc File: https://notefied-dynamic-precision.com/DB/Apps/Desktop/Item/Object.aspx?id=114560; BU Name: TEXAS INSTRUMENTS NORWAY; Budget Currency: EUR; Budget Price: 0.014; Budgetary Price: .014 EUR; Client Status: UNDER_REVIEW; Country of Origin: China, Israel; Datasheet URL: https://www.vishay.com/docs/20035/dcrcwe3.pdf; Datasheet URL 1: http://www.vishay.com/docs/20035/dcrcwe3.pdf; Datasheet URL 2: N/A; Definied Quality: INDUSTRIAL; Esd Level: N/A; Lead Time: 18; LifeCycle Status: ACTIVE; MPN: RESISTOR_0402_2.2k_+/-5%_50V_0.063W_M_+/-200ppm; MPN Status: ACTIVE; MSL: N/A; MTBF: N/A; MTBF Standard: N/A; Manufacturer: MANUFACTURER SELECTION; Mass: 0.00065g; Max Oper Temp: +155DEGC; Max TC: +200PPM/DEGC; Max Tol: +5%; Maximum Operating Temperature: +155DEGC; Maximum Temperature Coefficient: +200PPM/DEGC; Maximum Tolerance: +5%; Min Oper Temp: -55DEGC; Min TC: -200PPM/DEGC; Min Tol: -5%; Minimum Operating Temperature: -55DEGC; Minimum Temperature Coefficient: -200PPM/DEGC; Minimum Temperature Coeficient: -200PPM/DEGC; Minimum Tolerance: -5%; Mounting Type: SMD; NOTE Status: PREFERRED; NOTEfied URL: https://dev-webinterface.dpserver.no/item/7253343; Notes: Standard item: Duplicate Reason: custom footprint for TEXAS INSTRUMENTS NORWAY.; Old Footprint: RESC1005X40N; PCB Package: 0402; Packing Size: 10000; Packing Type: Tape & Reel; Part Number: 01-22487; Part Type: Resistor|0402|STANDARD; REACH/SVHC Compliance: Compliant; REACH/SVHC Details: SVHC List Version Jun 20, 2016; REACH/SVHC Source: Material Declaration; REACH/SVHC Status: Unaffected; REACH/SVHC_COMPLIANCE: COMPLIANT; REACH/SVHC_DETAILS: SVHC LIST VERSION Jun 20, 2016; REACH/SVHC_SOURCE: MATERIAL DECLARATION; REACH/SVHC_STATUS: UNAFFECTED; ROHS: Exempt; Rated Current: N/A; Rated Power: 0.063W; Rated Voltage: 50V; Resistor Type: THICK FILM; Revision: R024; RoHS Status: ROHS_COMPLIANT; Rtd Current: N/A; Rtd Power: 0.063W; Rtd Voltage: 50V; Status: Released; Texas Part Status: Under Review; Type: Resistor; Vendor: VISHAY; Vendor Part Number: CRCW04022K20JNED; Vendor Part Status: Active; WEIGHT: 0.00065g
R55 R56 = RESISTOR: RESISTOR, THICK FILM, 100, -5%/+5%, 0.063W, 50V, -55DEGC/+155DEGC, 0402, SMD; Additional Datasheet URL: https://www.vishay.com/en/product/20035/; AutoDoc File: https://notefied-dynamic-precision.com/DB/Apps/Desktop/Item/Object.aspx?id=114555; BU Name: TEXAS INSTRUMENTS NORWAY; Budget Currency: USD; Budget Price: 0.0014; Budgetary Price: .0014 USD; Client Status: UNDER_REVIEW; Country of Origin: China, Israel; Datasheet URL: https://www.vishay.com/docs/20035/dcrcwe3.pdf; Datasheet URL 1: http://www.vishay.com/docs/20035/dcrcwe3.pdf; Datasheet URL 2: N/A; Definied Quality: INDUSTRIAL; Esd Level: N/A; Lead Time: 16; LifeCycle Status: ACTIVE; MPN: RESISTOR_0402_100_+/-5%_50V_0.063W_M_+/-200ppm; MPN Status: ACTIVE; MSL: N/A; MTBF: N/A; MTBF Standard: N/A; Manufacturer: MANUFACTURER SELECTION; Mass: 0.00065g; Max Oper Temp: +155DEGC; Max TC: +200PPM/DEGC; Max Tol: +5%; Maximum Operating Temperature: +155DEGC; Maximum Temperature Coefficient: +200PPM/DEGC; Maximum Tolerance: +5%; Min Oper Temp: -55DEGC; Min TC: -200PPM/DEGC; Min Tol: -5%; Minimum Operating Temperature: -55DEGC; Minimum Temperature Coefficient: -200PPM/DEGC; Minimum Temperature Coeficient: -200PPM/DEGC; Minimum Tolerance: -5%; Mounting Type: SMD; NOTE Status: PREFERRED; NOTEfied URL: https://dev-webinterface.dpserver.no/item/7253339; Notes: Standard item: Duplicate Reason: custom footprint for TEXAS INSTRUMENTS NORWAY.; Old Footprint: RESC1005X40N; PCB Package: 0402; Packing Size: 10000; Packing Type: Tape & Reel; Part Number: 01-22482; Part Type: Resistor|0402|STANDARD; REACH/SVHC Compliance: Compliant; REACH/SVHC Details: SVHC List Version Jun 20, 2016; REACH/SVHC Source: Material Declaration; REACH/SVHC Status: Unaffected; REACH/SVHC_COMPLIANCE: COMPLIANT; REACH/SVHC_DETAILS: SVHC LIST VERSION Jun 20, 2016; REACH/SVHC_SOURCE: MATERIAL DECLARATION; REACH/SVHC_STATUS: UNAFFECTED; ROHS: Exempt; Rated Current: N/A; Rated Power: 0.063W; Rated Voltage: 50V; Resistor Type: THICK FILM; Revision: R027; RoHS Status: ROHS_COMPLIANT; Rtd Current: N/A; Rtd Power: 0.063W; Rtd Voltage: 50V; Status: Released; Texas Part Status: Under Review; Type: Resistor; Vendor: VISHAY; Vendor Part Number: CRCW0402100RJNED; Vendor Part Status: Active; WEIGHT: 0.00065g
R66 R67 = RESISTOR: RESISTOR, THICK FILM, 3.3k, -5%/+5%, 0.063W, 50V, -55DEGC/+155DEGC, 0402, SMD; Additional Datasheet URL: https://www.vishay.com/en/product/20035/; AutoDoc File: https://notefied-dynamic-precision.com/DB/Apps/Desktop/Item/Object.aspx?id=114561; BU Name: TEXAS INSTRUMENTS NORWAY; Budget Currency: EUR; Budget Price: 0.014; Budgetary Price: .014 EUR; Client Status: UNDER_REVIEW; Country of Origin: China, Israel; Datasheet URL: https://www.vishay.com/docs/20035/dcrcwe3.pdf; Datasheet URL 1: http://www.vishay.com/docs/20035/dcrcwe3.pdf; Datasheet URL 2: N/A; Definied Quality: INDUSTRIAL; Esd Level: N/A; Lead Time: 18; LifeCycle Status: ACTIVE; MPN: RESISTOR_0402_3.3k_+/-5%_50V_0.063W_M_+/-200ppm; MPN Status: ACTIVE; MSL: N/A; MTBF: N/A; MTBF Standard: N/A; Manufacturer: MANUFACTURER SELECTION; Mass: 0.00065g; Max Oper Temp: +155DEGC; Max TC: +200PPM/DEGC; Max Tol: +5%; Maximum Operating Temperature: +155DEGC; Maximum Temperature Coefficient: +200PPM/DEGC; Maximum Tolerance: +5%; Min Oper Temp: -55DEGC; Min TC: -200PPM/DEGC; Min Tol: -5%; Minimum Operating Temperature: -55DEGC; Minimum Temperature Coefficient: -200PPM/DEGC; Minimum Temperature Coeficient: -200PPM/DEGC; Minimum Tolerance: -5%; Mounting Type: SMD; NOTE Status: PREFERRED; NOTEfied URL: https://dev-webinterface.dpserver.no/item/7253348; Notes: Standard item: Duplicate Reason: custom footprint for TEXAS INSTRUMENTS NORWAY.; Old Footprint: RESC1005X40N; PCB Package: 0402; Packing Size: 10000; Packing Type: Tape & Reel; Part Number: 01-22488; Part Type: Resistor|0402|STANDARD; REACH/SVHC Compliance: Compliant; REACH/SVHC Details: SVHC List Version Jun 20, 2016; REACH/SVHC Source: Material Declaration; REACH/SVHC Status: Unaffected; REACH/SVHC_COMPLIANCE: COMPLIANT; REACH/SVHC_DETAILS: SVHC LIST VERSION Jun 20, 2016; REACH/SVHC_SOURCE: MATERIAL DECLARATION; REACH/SVHC_STATUS: UNAFFECTED; ROHS: Exempt; Rated Current: N/A; Rated Power: 0.063W; Rated Voltage: 50V; Resistor Type: THICK FILM; Revision: R024; RoHS Status: ROHS_COMPLIANT; Rtd Current: N/A; Rtd Power: 0.063W; Rtd Voltage: 50V; Status: Released; Texas Part Status: Under Review; Type: Resistor; Vendor: VISHAY; Vendor Part Number: CRCW04023K30JNED; Vendor Part Status: Active; WEIGHT: 0.00065g
R68 R69 = RESISTOR: RESISTOR, THICK FILM, JUMPER, 0, 0R/+0.05R, 0.1W, 1A, -55DEGC/+155DEGC, 0402, SMD; ALT_SYMBOLS: RESC1005X40A2L,RESC1005X40A2M; Additional Datasheet URL: https://industrial.panasonic.com/ww/products/pt/general-purpose-chip-resistors/models/ERJ2GE0R00X; Budgetary Price: .006 EUR; Country of Origin: China, Japan, Taiwan, Thailand; Datasheet URL: https://industrial.panasonic.com/cdbs/www-data/pdf/RDA0000/AOA0000C301.pdf; Lead Time: 20; Mass: 0.00063232g; Maximum Operating Temperature: +155DEGC; Maximum Temperature Coefficient: N/A; Maximum Tolerance: +0.05R; Minimum Operating Temperature: -55DEGC; Minimum Temperature Coefficient: N/A; Minimum Temperature Coeficient: N/A; Minimum Tolerance: 0R; Mounting Type: SMD; NOTEfied URL: https://dev-webinterface.dpserver.no/item/7218612; PCB Package: 0402; Packing Size: 10000; Packing Type: Tape & Reel; Part Number: 01-11470; Part Type: Resistor|0402|JUMPER; ROHS: Exempt; Rated Current: 1A; Rated Power: 0.1W; Rated Voltage: N/A; Resistor Type: THICK FILM; Revision: R056; Status: Released; Type: Resistor; Vendor: PANASONIC INDUSTRIAL; Vendor Part Number: ERJ2GE0R00X; Vendor Part Status: Active
SW1 SW2 = SWITCH_TACT_V2: SWITCH, TACTILE, 0.05A@12VDC, 0.05A@250VAC, SMD; ALT_SYMBOLS: SW_1188E1K2V_A2L,SW_1188E1K2V_A2M; Additional Datasheet URL: http://www.dip.com.tw/en/en-product-information/en-switch004/item/2445-1188; AutoDoc File: http://notefied-dynamic-precision.com/DB/Apps/Desktop/Item/Object.aspx?id=104642; Budgetary Price: .474 EUR; CLASS: IC; Country of Origin: China; Datasheet URL: http://www.dip.com.tw/en/en-product-information/en-switch004/item/download/2483_bfc264bcfe9982a2b01570916dd931c3; Datasheet URL 1: N/A; Datasheet URL 2: http://www.dip.com.tw/en/en-product-information/en-switch004; FPLIST: SW_1188E1K2V_A2N,SW_1188E1K2V_A2L,SW_1188E1K2V_A2M; Lead Time: 18; MPN: 1188E-1K2-V-TR; MPN Status: ACTIVE; Manufacturer: DIPTRONICS; Mass: N/A; Max Oper Temp: +70DEGC; Maximum Operating Temperature: +70DEGC; Min Oper Temp: -25DEGC; Minimum Operating Temperature: -25DEGC; Mounting Type: SMD; NOTE Status: PREFERRED; NOTEfied URL: https://dev-webinterface.dpserver.no/item/7329711; Packing Size: 1500; Packing Type: Tape & Reel; Part Number: 08-00293; Part Type: Switch|TACTILE; REACH/SVHC Compliance: Compliant; REACH/SVHC Details: SVHC List Version Dec 17, 2015; REACH/SVHC Source: REACH Declaration; REACH/SVHC Status: Unaffected; ROHS: Compliant; Rated Current: 0.05A; Rated Voltage: 12VDC; Revision: R021; RoHS Status: ROHS_COMPLIANT; Rtd Current: 0.05A; Rtd Voltage: 12V; Status: Released; Texas Part Status: Under Review; Type: Switch; Vendor: DIPTRONICS; Vendor Part Number: 1188E-1K2-V-TR; Vendor Part Status: Active
U3 = IC_FLASH_MX25R8035F_USON8: IC, MEMORY, FLASH, OTHER, 8Mbit, 8M X 1bit / 4M X 2bit / 2M X 4bit, 12ns, 1.65V TO 3.6V, uSON8, SMD; ALT_SYMBOLS: SON50P300X200X60-9B2L,SON50P300X200X60-9B2M; Additional Datasheet URL: https://www.macronix.com/en-us/products/NOR-Flash/Serial-NOR-Flash/Pages/spec.aspx?p=MX25R8035F&m=Serial%20NOR%20Flash&n=PM2164; AutoDoc File: http://notefied-dynamic-precision.com/DB/Apps/Desktop/Item/Object.aspx?id=104624; Budgetary Price: .42218 USD; Country of Origin: Taiwan; Datasheet URL: https://www.macronix.com/Lists/Datasheet/Attachments/8749/MX25R8035F,%20Wide%20Range,%208Mb,%20v1.6.pdf; Datasheet URL 1: N/A; Datasheet URL 2: http://www.macronix.com/Lists/DataSheet/Attachments/2570/MX25R8035F,%20Wide%20Range,%208Mb,%20v0.04.pdf; FPLIST: SON50P300X200X60-9B2N,SON50P300X200X60-9B2L,SON50P300X200X60-9B2M; Lead Time: 10; MPN Status: ACTIVE; Manufacturer: MACRONIX; Mass: N/A; Max Oper Temp: +85DEGC; Maximum Operating Temperature: +85DEGC; Min Oper Temp: -40DEGC; Minimum Operating Temperature: -40DEGC; Mounting Type: SMD; NOTE Status: PREFERRED; NOTEfied URL: https://dev-webinterface.dpserver.no/item/7497073; PCB Package: uSON8; Packing Size: 100; Packing Type: Tube; Part Number: 18-31726; Part Type: IC|MEMORY|FLASH|OTHER; REACH/SVHC Compliance: Compliant; REACH/SVHC Details: N/A; REACH/SVHC Source: REACH Declaration & Material Declaration; REACH/SVHC Status: Unaffected; ROHS: Compliant; Rated Voltage: 1.65V TO 3.6V; Revision: R023; RoHS Status: ROHS_COMPLIANT; Rtd Voltage: 1.65V TO 3.6V; Status: Released; Texas Part Status: Under Review; Type: IC; Vendor: MACRONIX; Vendor Part Status: Active

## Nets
5V0_BP: J1.2 P5.1 ; also on sheet 3
GND: C55.2 C81.2 C91.2 C92.2 CR1.1(C) CR2.1(C) J1.4 J2.2 P1.2 P1.3 P5.2 P5.3 P7.1(GND) P7.2(GND) SW1.1 SW1.2 SW1.3 SW2.1 SW2.2 SW2.4 U3.4(GND) U3.9(EGP) U5.3(GND) U5.6(GND) U5.20(GND) Z62.2 Z63.2 ; also on sheet 3 4
ANT-IN: U5.1(ANT-IN) Z61.1 Z62.1
ANT-MATCH: CA1.2 Z61.2 Z63.1
BP_RESET: J2.11 R52.1
BTN1: J2.16 P6.6 R56.2
BTN2: J2.18 P6.1 R55.2
DIO3: J1.15 R6.2
DIO3_X32P: C81.1 R6.1 U5.10(DIO3) Y1.1
DIO4: J1.9 R7.1
DIO4_X32N: C91.1 R7.2 U5.11(DIO4) Y1.2
DIO6: J1.7 U5.7(DIO6) ; also on sheet 3
DIO8: R69.1 U5.8(DIO8)
DIO8_SDA: P2.5 R69.2
DIO11: R19.1 R20.1 U5.19(DIO11)
DIO11_CS: J2.6 R19.2
DIO11_FLASH_CS: J2.5 R20.2 R24.1 U3.1(nCS)
DIO12: J2.12 U3.5(SI/SIO0) U5.16(DIO12)
DIO18: P6.5 U5.14(DIO18)
DIO20: J1.5 U5.15(DIO20) ; also on sheet 3
DIO21: P2.2 U5.13(DIO21)
DIO24: R68.2 U5.9(DIO24)
DIO24_A7_SCL: P6.2 R68.1
GLED: J2.1 P2.6 R15.2
LP_RESET: J2.10 R51.1
POCI: J2.14 P2.4 U3.2(SO/SIO1)
RF_UFL: CA2.1 P7.3(SIG)
RFIO: CA1.1 CA2.2 U5.2(RFIO)
RLED: J2.3 P2.1 R14.2
SCL: J1.17 P6.4 R67.1
SCLK: J1.13 P6.3 U3.6(SCLK)
SDA: J1.19 P2.3 R66.1
WMCU_RESET: C92.1 R1.1 R51.2 R52.2 U5.12(nRST) ; also on sheet 3
WMCU_SWDCK: R5.2 U5.17(DIO17/SWD_CLK) ; also on sheet 3
WMCU_SWDIO: R4.2 U5.18(DIO16/SWD_IO) ; also on sheet 3
WMCU_VDD: J1.1 P1.1 R1.2 R22.1 R23.1 R24.2 R25.2 R66.2 R67.2 U5.4(VDDS) U5.5(VDDS) ; also on sheet 3
N3109894: J2.13 R4.1
N3109960: J2.15 R5.1
N3110768: R56.1 SW1.4
N3110772: R55.1 SW2.3
N3110876: CR1.2(A) R15.1
N3110880: CR2.2(A) R14.1
N3111246: C55.1 R25.1 U3.8(VCC)
N3111262: R22.2 U3.7(nRST/SIO3)
N3111266: R23.2 U3.3(nWP/SIO2)

Not connected (* = marked no-connect by the designer): J1 3* 6* 8* 10* 11* 12* 14* 16* 18* 20*; J2 4* 7* 8* 9* 17* 19* 20*

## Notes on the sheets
sheet 1
- Wireless MCU RF
- Wireless MCU IO block placed on page 2
- Z1-Z3 for
  antenna matching
sheet 2
- BoosterPack Headers and Peripherals
- 40
- 20
- 1
- 2
- 21
- 22
- 38
- 39
- 18
- 19
- 5V and 3V headers
- 3
- 23
- 37
- 17
- 4
- 24
- 36
- 16
- 5
- 25
- 35
- 15
- 6
- 26
- 34
- 14
- 7
- 8
- 27
- 28
- 32
- 33
- 12
- 13
- 9
- 29
- 31
- 11
- 10
- 30
- Wireless MCU IO block
- External flash
- Buttons / LEDs
- If external flash mounted, default to FLASH_CS
- SPI 2-4, RLED 2-1
  I2C 5-3, GLED 5-6
- I2C 2-4, BTN2 2-1
  SPI 5-3, BTN1 5-6
